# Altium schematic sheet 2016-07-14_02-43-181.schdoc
size 292 x 119 mm; SheetNumber: 1; SheetTotal: 1
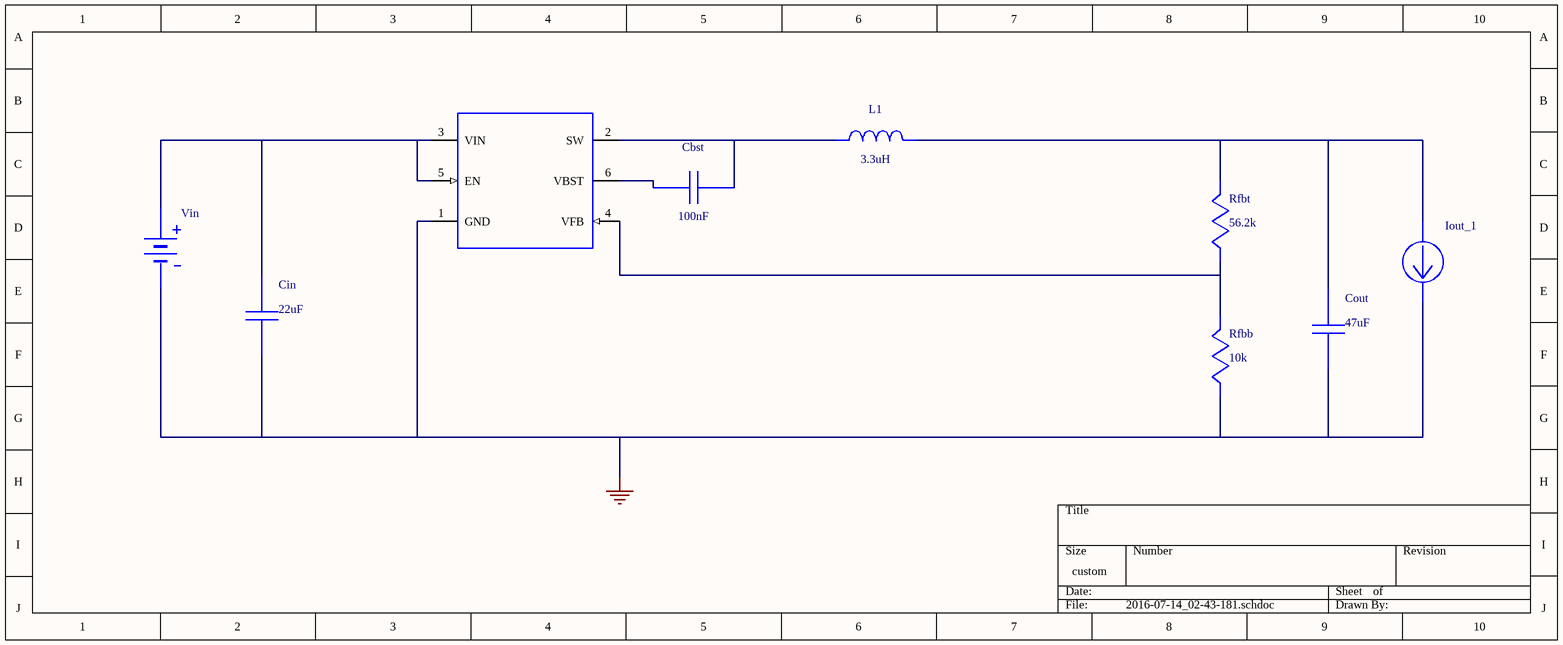
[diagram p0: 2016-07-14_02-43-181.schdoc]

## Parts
Cbst  value 100nF  (hidden comment: 08053C104KAT2A)
Cin  value 22uF  (hidden comment: GRM32ER61E226KE15L)
Cout  value 47uF  (hidden comment: C3216JB1A476M)
Iout_1  WB_CURRENT_LOAD  (value not drawn)
L1  value 3.3uH  (hidden comment: SRR6038-3R3Y)
Rfbb  value 10k  (hidden comment: CRCW040210K0FKED)
Rfbt  value 56.2k  (hidden comment: CRCW040256K2FKED)
U1  TPS563200DDCR  (value not drawn)
Vin  WB_BATTERY  (value not drawn)

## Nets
0: Cin.2 Cout.2 Iout_1.2(-) Rfbb.2 U1.1(GND) Vin.2(-)
NetCbst_1: Cbst.1 L1.1 U1.2(SW)
NetCbst_2: Cbst.2 U1.6(VBST)
NetCin_1: Cin.1 U1.3(VIN) U1.5(EN) Vin.1(+)
NetCout_1: Cout.1 Iout_1.1(+) L1.2 Rfbt.1
NetRfbb_1: Rfbb.1 Rfbt.2 U1.4(VFB)

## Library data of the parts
Cbst = 08053C104KAT2A: Manufacturer Name: AVX
Cin = GRM32ER61E226KE15L: GRM32ER61E226KE1; Manufacturer Name: MuRata
Cout = C3216JB1A476M: Manufacturer Name: TDK
L1 = SRR6038-3R3Y: Manufacturer Name: Bourns
Rfbb = CRCW040210K0FKED: Manufacturer Name: Vishay-Dale
Rfbt = CRCW040256K2FKED: Manufacturer Name: Vishay-Dale
U1 = TPS563200DDCR: Manufacturer Name: Texas Instruments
